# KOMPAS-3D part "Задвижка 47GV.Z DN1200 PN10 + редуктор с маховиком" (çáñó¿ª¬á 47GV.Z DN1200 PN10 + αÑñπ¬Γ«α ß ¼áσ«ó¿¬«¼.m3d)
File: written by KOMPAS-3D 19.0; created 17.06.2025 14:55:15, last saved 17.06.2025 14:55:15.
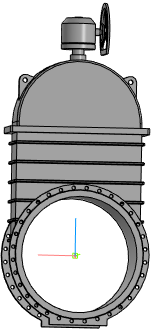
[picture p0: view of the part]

Document properties: Полное имя файла: Задвижка 47GV.Z DN1200 PN10 + редуктор с маховиком.a3d

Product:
- Part/product: Задвижка 47GV.Z DN1200 PN10 + редуктор с маховиком
    Масса: 6477.55

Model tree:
1. Операция без истории:1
